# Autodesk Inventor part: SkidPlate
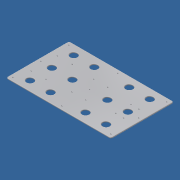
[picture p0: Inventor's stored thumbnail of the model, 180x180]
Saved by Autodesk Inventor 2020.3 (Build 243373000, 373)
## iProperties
Created: 2020-09
Part Number: SkidPlate
Material: UHMW, White
Document SubType Name: Modeling
Designer: biggshj
Manufacturer: Standard
Standards Organization: Custom
Mass: 7315.1 g
Surface Area: 16271 cm^2
Volume: 7782.02 cm^3
Density: 0.94 g/cm^3
Appearance: Smooth - White
Sheet Metal Width: 0.000 mm
Sheet Metal Length: 0.000 mm
Sheet Metal Area: 0.000 mm^2
Sheet Metal Rule: Default
Company: NIWA Instrument Systems
Author: biggshj
Revision Number: 1
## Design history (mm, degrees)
derived "BasePlate.ipt"
sketch "Sketch12"
  geometry: L1 (0, 0)-(1200, 0) reference; L2 (1200, 700)-(1200, 0) reference; L3 (1200, 700)-(0, 700) reference; L4 (0, 0)-(0, 700) reference; L5 (1200, -10)-(0, -10) reference; L6 (0, 0)-(0, -10) reference; L7 (0, 710)-(0, 700) reference; L8 (0, 710)-(1200, 710) reference; L9 (1200, 700)-(1200, 710) reference; L10 (1200, -10)-(1200, 0) reference; C1 r 4.25 at (680, 225) reference; C2 r 4.25 at (680, 475) reference; C3 r 4.25 at (520, 225) reference; C4 r 4.25 at (520, 475) reference; C5 r 4.25 at (80, 200) reference; C6 r 4.25 at (250, 500) reference; C7 r 4.25 at (80, 500) reference; C8 r 4.25 at (250, 200) reference; C9 r 40 at (1035, 600) reference; C10 r 40 at (800, 600) reference; C11 r 40 at (1035, 350) reference; C12 r 40 at (1035, 100) reference; C13 r 40 at (800, 100) reference; C14 r 40 at (800, 350) reference; C15 r 40 at (165, 600) reference; C16 r 40 at (400, 600) reference; C17 r 40 at (165, 350) reference; C18 r 40 at (165, 100) reference; C19 r 40 at (400, 100) reference; C20 r 40 at (400, 350) reference; C21 r 4.025 at (1160, 670) reference; C22 r 4.025 at (600, 670) reference; C23 r 4.025 at (40, 670) reference; C24 r 4.025 at (1160, 350) reference; C25 r 4.025 at (40, 350) reference; C26 r 4.025 at (1160, 30) reference; C27 r 4.025 at (600, 30) reference; C28 r 4.025 at (40, 30) reference; C29 r 4.025 at (600, 350) reference; C30 r 4.25 at (985, 262.514) reference; C31 r 4.25 at (1075, 437.486) reference; C32 r 4.25 at (1075, 262.514) reference; C33 r 4.25 at (985, 437.486) reference; 1 further point
extrude "Extrusion11" new body sketch "Sketch12" distance "d104" = 10; taper "d105" = 0 deg
fillet "Fillet10" dims "d106" = 20
fillet "Fillet11" dims "d107" = 6
chamfer "Chamfer4" distance "d108" = 5; stored, may be unused: second distance "d109" = 2, angle "d110" = 45 deg
body "Solid1"
tag "TaggingFeature1"
body "Solid4"
feature "Solid1::BasePlate.ipt"
body "Srf1"
node "Project Cut Edges1"
other parameters: "Thickness" = 6 (derived), "KFactor" = 4.4, "BendRadius" = 6 (= Thickness), "BendReliefWidth" = 6 (= Thickness), "BendReliefDepth" = 3 (= 0.5 x Thickness), "CornerReliefSize" = 24 (= 4 x Thickness), "SeamGap" = 0.01, "MinimumRemnant" = 12 (= 2 x Thickness), "TransitionRadius" = 6 (= BendRadius), "JacobiRadiusSize" = 6 (= Thickness), "GapSize" = 6 (= Thickness)
